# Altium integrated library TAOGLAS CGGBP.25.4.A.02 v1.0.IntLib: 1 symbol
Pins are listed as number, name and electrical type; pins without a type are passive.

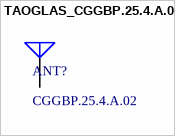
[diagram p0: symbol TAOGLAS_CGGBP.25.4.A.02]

## TAOGLAS_CGGBP.25.4.A.02
designator ANT?, comment CGGBP.25.4.A.02
Embedded 25mm GPS/GLONASS/Galileo/BeiDou Patch Antenna, 1561/1575/1602MHz; ComponentLibStatus: Created; MFG: Taoglas; Temp_High: +85C; Temp_Low: -40C
footprint TAOGLAS_CGGBP.25.4.A.02 (Embedded 25mm GPS/GLONASS/Galileo/BeiDou Patch Antenna, 1561/1575/1602MHz)
pins: 1 RF FEED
